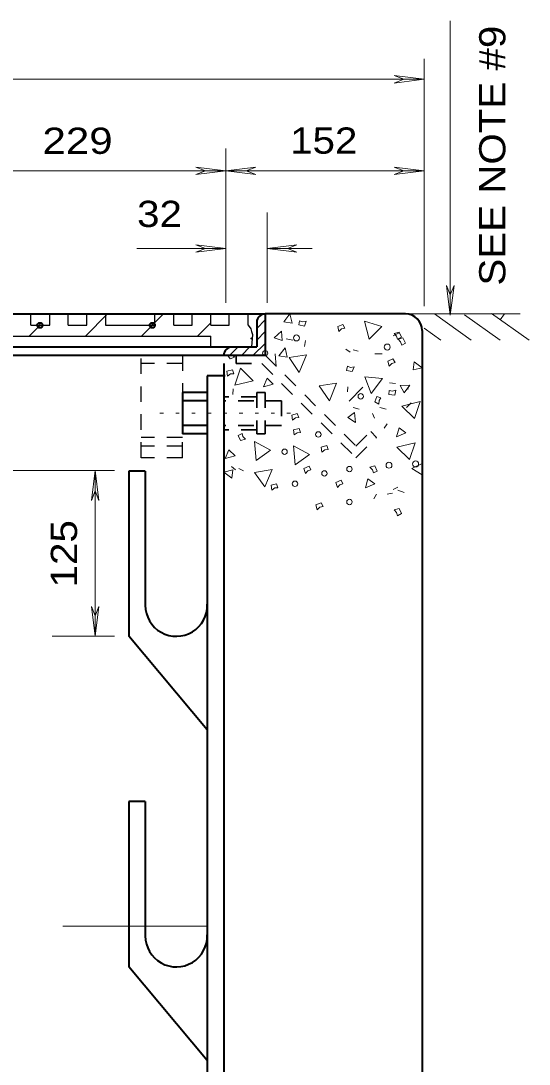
# Model space of a CAD drawing. Extents: x 312583 to 312854, y 144419 to 144597.
# Drawn here: x 312726 to 312740.74, y 144495.47 to 144525.72 of the extents above; entities that cross this region are included whole.
import ezdxf

# ---------------------------------------------------------------- set-up
doc = ezdxf.new("R2010")
doc.units = 0
doc.header["$LTSCALE"] = 0.3
doc.header["$PDMODE"] = 32
doc.header["$PDSIZE"] = 0.15
doc.linetypes.add('DOTTED', pattern=[1.5, 0.3, -1.2])
doc.linetypes.add('SHORT_DASHED', pattern=[2.7, 1.5, -1.2])
doc.layers.add('1', color=7, linetype='Continuous', lineweight=40)
doc.layers.add('2', color=7, linetype='Continuous', lineweight=13)

msp = doc.modelspace()

# ---------------------------------------------------------------- linework, layer by layer
at = {"layer": '1'}
for p, q in [((312709.3672, 144517.2205), (312733.0878, 144517.2205)), ((312732.8425, 144516.9829), (312732.8425, 144516.2622)), ((312733.0878, 144517.2205), (312733.0878, 144516.0245)), ((312737.1588, 144517.2205), (312733.0878, 144517.2205)), ((312737.6342, 144516.7375), (312737.6495, 144471.2205)), ((312713.5608, 144516.2622), (312732.8425, 144516.2622)), ((312713.3155, 144516.0245), (312733.0878, 144516.0245)), ((312731.8842, 144515.7792), (312731.8995, 144471.2205)), ((312731.9225, 144515.4265), (312731.4088, 144515.4265)), ((312731.4088, 144515.4265), (312731.4088, 144483.9165)), ((312730.6882, 144514.9435), (312730.6882, 144513.7475)), ((312731.4088, 144514.9435), (312730.6882, 144514.9435)), ((312731.4088, 144514.7059), (312730.6882, 144514.7059)), ((312731.4088, 144513.9852), (312730.6882, 144513.9852)), ((312731.4088, 144513.7475), (312730.6882, 144513.7475)), ((312729.1318, 144512.6665), (312729.1318, 144507.8749)), ((312729.6072, 144512.6665), (312729.1318, 144512.6665)), ((312729.6072, 144512.6665), (312729.6072, 144508.7719)), ((312731.4088, 144505.1609), (312729.1318, 144507.8749)), ((312731.4088, 144504.3635), (312731.4088, 144503.7349)), ((312731.8918, 144504.3635), (312731.8918, 144503.7349)), ((312729.1318, 144503.0832), (312729.1318, 144498.2915)), ((312729.6072, 144503.0832), (312729.1318, 144503.0832)), ((312729.6072, 144503.0832), (312729.6072, 144499.1885)), ((312731.4088, 144495.5775), (312729.1318, 144498.2915))]:
    msp.add_line(p, q, dxfattribs=at)
at = {"layer": '1', "lineweight": 25}
for p, q in [((312726.2952, 144516.8985), (312726.2952, 144517.2205)), ((312726.8395, 144516.8985), (312726.8395, 144517.2205)), ((312727.3762, 144516.8985), (312727.3762, 144517.2205)), ((312727.8745, 144516.5765), (312728.5185, 144517.2205)), ((312727.9128, 144516.8985), (312727.9128, 144517.2205)), ((312728.4572, 144517.2205), (312728.4572, 144516.8985)), ((312729.4998, 144516.5765), (312730.1438, 144517.2205)), ((312729.8908, 144516.8985), (312729.8908, 144517.2205)), ((312730.4352, 144516.8985), (312730.4352, 144517.2205)), ((312730.9718, 144516.8985), (312730.9718, 144517.2205)), ((312731.1252, 144516.5765), (312731.5085, 144516.9599)), ((312731.5085, 144516.8985), (312731.5085, 144517.2205)), ((312732.0452, 144516.8985), (312732.0452, 144517.2205)), ((312726.2492, 144516.5765), (312726.5635, 144516.8985)), ((312727.3762, 144516.8985), (312727.7595, 144516.8985)), ((312727.6752, 144516.8985), (312727.9128, 144516.8985)), ((312728.4572, 144516.8985), (312729.1855, 144516.8985)), ((312729.1855, 144516.8985), (312729.8908, 144516.8985)), ((312724.3248, 144516.5765), (312731.5085, 144516.5765)), ((312731.5085, 144516.2622), (312731.5085, 144516.5765))]:
    msp.add_line(p, q, dxfattribs=at)
at = {"layer": '1', "linetype": 'SHORT_DASHED', "lineweight": 25}
for p, q in [((312734.8818, 144517.2205), (312734.4065, 144517.2205)), ((312729.4922, 144513.0499), (312729.4922, 144516.0245)), ((312730.6882, 144515.7792), (312729.4922, 144515.7792)), ((312730.6882, 144516.0245), (312730.6882, 144514.9435)), ((312730.6882, 144513.6402), (312729.4922, 144513.6402)), ((312730.6882, 144513.0499), (312730.6882, 144513.7475)), ((312730.6882, 144513.3872), (312729.4922, 144513.3872)), ((312730.6882, 144513.0499), (312729.4922, 144513.0499))]:
    msp.add_line(p, q, dxfattribs=at)
at = {"layer": '1', "linetype": 'SHORT_DASHED', "lineweight": 35}
for p, q in [((312732.2445, 144516.0245), (312732.2445, 144515.7792)), ((312732.2445, 144515.7792), (312732.9882, 144515.7792)), ((312732.9882, 144515.7792), (312735.7175, 144513.0499)), ((312733.0878, 144516.0245), (312735.7175, 144513.3872)), ((312732.8425, 144514.9435), (312732.8425, 144513.7475)), ((312733.0878, 144514.9435), (312732.8425, 144514.9435)), ((312733.0878, 144514.9435), (312733.0878, 144513.7475)), ((312732.8425, 144514.8209), (312731.8842, 144514.8209)), ((312733.5632, 144514.7059), (312731.8842, 144514.7059)), ((312733.5632, 144514.7059), (312733.5632, 144513.9852)), ((312733.5632, 144513.9852), (312731.8842, 144513.9852)), ((312732.8425, 144513.8625), (312731.8842, 144513.8625)), ((312733.0878, 144513.7475), (312732.8425, 144513.7475)), ((312735.7175, 144513.3872), (312736.1468, 144513.8089)), ((312735.7175, 144513.0499), (312736.3155, 144513.6402)), ((312736.1468, 144513.8089), (312736.3155, 144513.6402))]:
    msp.add_line(p, q, dxfattribs=at)
at = {"layer": '1', "linetype": 'DOTTED', "lineweight": 13}
msp.add_line((312730.0365, 144514.3455), (312733.8545, 144514.3455), dxfattribs=at)
at = {"layer": '1', "lineweight": 25}
for points in [[(312726.2952, 144516.8985), (312726.5405, 144516.8985), (312726.8395, 144516.8985)], [(312730.4352, 144516.8985), (312730.7188, 144516.8985), (312730.9718, 144516.8985)], [(312731.5085, 144516.8985), (312731.7768, 144516.8985), (312732.0452, 144516.8985)]]:
    msp.add_lwpolyline(points, dxfattribs=at)
at = {"layer": '1'}
for points in [[(312731.4088, 144504.2179), (312731.4088, 144504.0952), (312731.4088, 144503.7349)], [(312731.8918, 144504.2179), (312731.8918, 144504.0952), (312731.8918, 144503.7349)]]:
    msp.add_lwpolyline(points, dxfattribs=at)
for centre, radius, start, end in [((312733.084, 144516.98), 0.2396, 90, 180), ((312737.1569, 144516.7404), 0.4792, 0, 90), ((312732.1257, 144516.0217), 0.2396, 90, 180), ((312730.509, 144508.7743), 0.8984, 180.03057, 1.87136), ((312730.509, 144499.1909), 0.8984, 180.03057, 1.87136)]:
    msp.add_arc(centre, radius, start, end, dxfattribs=at)
for p in [(312726.5558, 144516.8909), (312729.8142, 144516.8909)]:
    msp.add_point(p, dxfattribs=at)
at = {"layer": '2'}
for p, q in [((312738.4545, 144517.1822), (312738.4545, 144525.7152)), ((312737.6955, 144517.4429), (312737.6955, 144524.6189)), ((312708.8842, 144524.0209), (312737.6955, 144524.0209)), ((312736.8292, 144524.1282), (312737.1052, 144524.0209)), ((312737.6955, 144524.0209), (312736.8292, 144524.1282)), ((312736.8292, 144523.9135), (312737.1052, 144524.0209)), ((312737.6955, 144524.0209), (312736.8292, 144523.9135)), ((312731.9455, 144517.5425), (312731.9455, 144522.0199)), ((312731.0792, 144521.4755), (312731.3552, 144521.3682)), ((312731.9455, 144521.3682), (312731.0792, 144521.4755)), ((312731.0792, 144521.2609), (312731.3552, 144521.3682)), ((312731.9455, 144521.3682), (312731.0792, 144521.2609)), ((312731.9455, 144521.3682), (312732.8118, 144521.4755)), ((312731.9455, 144521.3682), (312737.6955, 144521.3682)), ((312731.9455, 144521.3682), (312732.8118, 144521.2609)), ((312732.8118, 144521.4755), (312732.5358, 144521.3682)), ((312732.8118, 144521.2609), (312732.5358, 144521.3682)), ((312736.8292, 144521.4755), (312737.1052, 144521.3682)), ((312737.6955, 144521.3682), (312736.8292, 144521.4755)), ((312736.8292, 144521.2609), (312737.1052, 144521.3682)), ((312737.6955, 144521.3682), (312736.8292, 144521.2609)), ((312733.1415, 144517.5425), (312733.1415, 144520.1645)), ((312729.3618, 144519.1142), (312731.9455, 144519.1142)), ((312731.0792, 144519.2215), (312731.3552, 144519.1142)), ((312731.9455, 144519.1142), (312731.0792, 144519.2215)), ((312731.0792, 144519.0069), (312731.3552, 144519.1142)), ((312731.9455, 144519.1142), (312731.0792, 144519.0069)), ((312733.1415, 144519.1142), (312734.0078, 144519.2215)), ((312733.1415, 144519.1142), (312734.4448, 144519.1142)), ((312733.1415, 144519.1142), (312734.0078, 144519.0069)), ((312734.0078, 144519.2215), (312733.7318, 144519.1142)), ((312734.0078, 144519.0069), (312733.7318, 144519.1142)), ((312738.3472, 144518.0485), (312738.4545, 144517.7725)), ((312738.4545, 144517.1822), (312738.3472, 144518.0485)), ((312738.5618, 144518.0485), (312738.4545, 144517.7725)), ((312738.4545, 144517.1822), (312738.5618, 144518.0485)), ((312732.8425, 144516.7989), (312733.0878, 144517.0442)), ((312737.1588, 144517.2205), (312740.4785, 144517.2205)), ((312737.6955, 144517.2205), (312740.1948, 144517.2205)), ((312739.0602, 144516.4615), (312737.9945, 144517.2205)), ((312739.9035, 144516.4615), (312738.8608, 144517.1975)), ((312740.7392, 144516.4615), (312739.6505, 144517.2282)), ((312740.0262, 144517.2205), (312739.9035, 144517.0519)), ((312732.8425, 144516.4615), (312733.0878, 144516.7069)), ((312736.9672, 144516.6685), (312736.7985, 144516.5842)), ((312738.1785, 144516.4615), (312737.6955, 144516.8065)), ((312732.7428, 144516.0245), (312733.0878, 144516.3619)), ((312733.6935, 144516.4999), (312733.8852, 144516.4615)), ((312734.2532, 144516.4539), (312734.2302, 144516.2775)), ((312732.0605, 144516.0245), (312732.3058, 144516.2622)), ((312732.4055, 144516.0245), (312732.6432, 144516.2622)), ((312733.4098, 144515.6949), (312733.3792, 144516.0629)), ((312735.4262, 144516.2009), (312735.5488, 144516.1165)), ((312735.6408, 144516.1779), (312735.7865, 144516.1395)), ((312736.4765, 144516.0629), (312736.2618, 144516.0629)), ((312736.8675, 144515.2042), (312736.6912, 144515.2272)), ((312732.1525, 144514.8822), (312732.1602, 144515.0509)), ((312735.4798, 144515.1045), (312735.4722, 144514.9589)), ((312735.5182, 144514.6905), (312735.9168, 144515.0969)), ((312737.2278, 144515.0432), (312737.2202, 144515.0509)), ((312737.2202, 144515.0432), (312737.2278, 144515.0432)), ((312737.1818, 144514.5065), (312737.3198, 144514.6445)), ((312735.6408, 144514.5065), (312735.8095, 144514.4605)), ((312736.2542, 144514.1999), (312736.2005, 144514.3379)), ((312736.4075, 144514.5065), (312736.5915, 144514.4605)), ((312736.6222, 144514.0312), (312736.5378, 144513.9085)), ((312732.1142, 144512.7969), (312732.2292, 144512.6972)), ((312732.3212, 144512.7432), (312732.4592, 144512.6742)), ((312728.7178, 144512.6819), (312723.8648, 144512.6819)), ((312728.1582, 144512.6819), (312728.0508, 144511.8155)), ((312728.1582, 144512.6819), (312728.1582, 144507.8749)), ((312728.1582, 144512.6819), (312728.2655, 144511.8155)), ((312736.7985, 144512.1299), (312736.9288, 144512.1989)), ((312728.0508, 144511.8155), (312728.1582, 144512.0915)), ((312728.2655, 144511.8155), (312728.1582, 144512.0915)), ((312736.3155, 144511.9919), (312736.2388, 144511.8615)), ((312736.6222, 144511.9995), (312736.7755, 144512.0225)), ((312737.1128, 144512.0455), (312736.9365, 144512.1069)), ((312728.0508, 144508.7412), (312728.1582, 144508.4652)), ((312728.1582, 144507.8749), (312728.0508, 144508.7412)), ((312728.2655, 144508.7412), (312728.1582, 144508.4652)), ((312728.1582, 144507.8749), (312728.2655, 144508.7412)), ((312728.7178, 144507.8749), (312726.9085, 144507.8749)), ((312731.4088, 144499.4722), (312727.2228, 144499.4722))]:
    msp.add_line(p, q, dxfattribs=at)
at = {"layer": '2', "lineweight": 25}
for p, q in [((312732.5895, 144516.8985), (312732.5895, 144517.2205)), ((312732.6662, 144516.4922), (312732.7045, 144516.5305))]:
    msp.add_line(p, q, dxfattribs=at)
at = {"layer": '2'}
for points in [[(312714.6955, 144521.3682), (312723.2668, 144521.3682), (312731.9455, 144521.3682)], [(312731.9992, 144516.0245), (312732.0682, 144515.9172), (312732.1985, 144515.9709), (312732.1372, 144516.0245)], [(312737.6342, 144512.8889), (312737.3352, 144512.7355), (312737.6342, 144512.5515)]]:
    msp.add_lwpolyline(points, dxfattribs=at)
for points in [[(312733.6245, 144516.9905), (312733.8698, 144516.9522), (312733.8008, 144517.2205)], [(312734.1688, 144516.9905), (312734.0845, 144517.0212), (312734.0615, 144516.9062), (312734.2225, 144516.8679), (312734.2762, 144517.0059)], [(312736.1008, 144516.4845), (312736.4688, 144516.8525), (312735.9705, 144517.0135)], [(312733.3485, 144516.5229), (312733.5785, 144516.4462), (312733.5555, 144516.7222)], [(312735.3035, 144516.7835), (312735.3955, 144516.8065), (312735.3342, 144516.9139), (312735.1885, 144516.8525), (312735.2268, 144516.7069)], [(312736.8982, 144516.5765), (312736.9212, 144516.4845), (312737.0362, 144516.5459), (312736.9672, 144516.6915), (312736.8292, 144516.6532)], [(312737.0132, 144516.4079), (312737.0438, 144516.3159), (312737.1512, 144516.3772), (312737.0822, 144516.5229), (312736.9442, 144516.4845)], [(312733.4865, 144516.0015), (312733.7242, 144515.9709), (312733.6628, 144516.2392)], [(312734.2838, 144516.0322), (312733.7778, 144515.9555), (312734.0768, 144515.5262)], [(312736.7602, 144515.7792), (312736.8522, 144515.8099), (312736.7908, 144515.9172), (312736.6452, 144515.8482), (312736.6835, 144515.7102)], [(312737.4042, 144515.8329), (312737.3735, 144515.5952), (312737.6342, 144515.6565)], [(312732.0835, 144515.4802), (312732.1755, 144515.4879), (312732.1372, 144515.6029), (312731.9762, 144515.5645), (312731.9992, 144515.4189)], [(312732.7352, 144515.2809), (312732.3748, 144515.6489), (312732.2062, 144515.1505)], [(312735.5565, 144515.6719), (312735.4722, 144515.7025), (312735.4492, 144515.5799), (312735.6102, 144515.5492), (312735.6638, 144515.6872)], [(312733.3178, 144515.1889), (312733.1415, 144515.3575), (312733.0418, 144515.1045)], [(312735.1578, 144515.2119), (312734.6518, 144515.1352), (312734.9508, 144514.7059)], [(312736.4842, 144515.3499), (312735.9782, 144515.3959), (312736.1622, 144514.9129)], [(312736.9978, 144515.1429), (312737.1205, 144514.9359), (312737.2815, 144515.1582)], [(312736.7755, 144514.9819), (312736.6835, 144515.0049), (312736.6758, 144514.8822), (312736.8445, 144514.8669), (312736.8752, 144515.0125)], [(312736.3922, 144514.7135), (312736.4382, 144514.7902), (312736.3232, 144514.8285), (312736.2618, 144514.6752), (312736.3845, 144514.6062)], [(312737.0515, 144514.5449), (312737.4195, 144514.1845), (312737.5805, 144514.6829)], [(312733.9618, 144514.2075), (312734.0615, 144514.2152), (312734.0155, 144514.3302), (312733.8622, 144514.2842), (312733.8775, 144514.1385)], [(312735.6715, 144514.3609), (312735.4798, 144514.2152), (312735.7098, 144514.0772)], [(312732.4438, 144513.6632), (312732.4208, 144513.7552), (312732.3058, 144513.6939), (312732.3748, 144513.5482), (312732.5128, 144513.5865)], [(312734.0155, 144513.7782), (312734.1075, 144513.7859), (312734.0692, 144513.9009), (312733.9082, 144513.8625), (312733.9312, 144513.7169)], [(312737.1665, 144513.7705), (312736.9672, 144513.9162), (312736.8982, 144513.6555)], [(312732.8272, 144512.9732), (312733.2412, 144513.2722), (312732.7812, 144513.5175)], [(312733.9542, 144512.8505), (312734.3682, 144513.1495), (312733.9082, 144513.3949)], [(312734.8205, 144513.2799), (312734.9125, 144513.2875), (312734.8742, 144513.4025), (312734.7132, 144513.3565), (312734.7285, 144513.2109)], [(312736.9058, 144513.3565), (312737.2662, 144512.9962), (312737.4348, 144513.4869)], [(312732.2138, 144513.1112), (312732.0375, 144513.2799), (312731.9302, 144513.0269)], [(312734.3222, 144512.6742), (312734.4142, 144512.6972), (312734.3605, 144512.8045), (312734.2072, 144512.7355), (312734.2532, 144512.5975)], [(312736.2005, 144512.7049), (312736.2235, 144512.6129), (312736.3308, 144512.6665), (312736.2618, 144512.8199), (312736.1238, 144512.7739)], [(312732.1218, 144512.4595), (312732.1525, 144512.6972), (312731.8842, 144512.6359)], [(312733.2872, 144512.7125), (312732.7735, 144512.6282), (312733.0802, 144512.2065)], [(312736.2618, 144512.2985), (312736.0625, 144512.4442), (312735.9935, 144512.1835)], [(312733.3638, 144512.1759), (312733.4558, 144512.1835), (312733.4175, 144512.2985), (312733.2565, 144512.2525), (312733.2795, 144512.1069)], [(312735.2498, 144512.2679), (312735.3418, 144512.2909), (312735.2882, 144512.3982), (312735.1348, 144512.3369), (312735.1808, 144512.1912)], [(312734.6748, 144511.6162), (312734.7668, 144511.6392), (312734.7055, 144511.7465), (312734.5598, 144511.6852), (312734.5982, 144511.5395)], [(312736.8982, 144511.4629), (312736.9212, 144511.3709), (312737.0362, 144511.4322), (312736.9672, 144511.5779), (312736.8292, 144511.5395)]]:
    msp.add_lwpolyline(points, close=True, dxfattribs=at)
at = {"layer": '2', "lineweight": 25}
msp.add_lwpolyline([(312732.5895, 144516.8985), (312732.6662, 144516.7835), (312732.6892, 144516.7145), (312732.6968, 144516.6839), (312732.7198, 144516.6225), (312732.6892, 144516.2622)], dxfattribs=at)
at = {"layer": '2'}
for centre, radius in [((312733.9933, 144516.5247), 0.0865), ((312736.6253, 144516.2599), 0.0865), ((312735.8576, 144514.8305), 0.0784), ((312734.6281, 144513.7265), 0.0784), ((312733.6496, 144513.2253), 0.0784), ((312735.5308, 144512.7231), 0.0784), ((312736.6764, 144512.8341), 0.0865), ((312737.4476, 144512.871), 0.0865), ((312734.8035, 144512.5976), 0.0784), ((312733.9506, 144512.2966), 0.0784), ((312735.5308, 144511.7696), 0.0784)]:
    msp.add_circle(centre, radius, dxfattribs=at)
msp.add_point((312733.0878, 144516.0859), dxfattribs=at)

# ---------------------------------------------------------------- texts
at = {"layer": '2', "width": 1.15}
for s, p in [('SEE NOTE #9', (312740.0503, 144518.0409)), ('125 ', (312727.6324, 144509.293))]:
    msp.add_text(s, height=0.76, rotation=90, dxfattribs=at).set_placement(p)
at = {"layer": '2'}
for s, width, p in [('229 ', 1.2, (312726.6299, 144521.8599)), ('152 ', 1.15, (312733.8095, 144521.8656)), ('32 ', 1.15, (312729.3734, 144519.74))]:
    msp.add_text(s, height=0.76, dxfattribs=dict(at, width=width)).set_placement(p)

doc.saveas('drawing.dxf')
